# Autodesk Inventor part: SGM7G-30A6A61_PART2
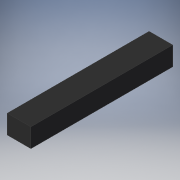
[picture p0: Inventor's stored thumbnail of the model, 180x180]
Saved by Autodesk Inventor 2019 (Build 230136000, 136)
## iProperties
Created: 2019-07
Part Number: SGM7G-30A6A61_PART2
Material: Generic
Catalog Web Link: www.cadenas.de
Description: -
Vendor: YASKAWAUSA
Document SubType Name: Modeling
Designer: psAdmin
Manufacturer: YASKAWAUSA
Mass: 4.8 g
Surface Area: 23.2 cm^2
Volume: 4.8 cm^3
Density: 1 g/cm^3
Appearance: PSOLRGB-175-175-175
Category: PARTsolutions
Company: YASKAWAUSA
Title: SGM7G-30A6A61_PART2
Author: Cadenas PARTsolutions
Sending System: PARTsolutions
PSOL_IDENT_0: {$CADENAS_DATA/23d-libs/yaskawa_usa/motion/sigma_7_servo_products/rotary_servo_motors/sgm7g.prj},198
PSOL_IDENT_1: {VTYP=3D},{NB=SGM7G-30A6A61_PART2},{LINA=SGM7G-30A6A61_PART2},{NN=SGM7G_PART2},{NOPRJ=TRUE},{DATE=2
PSOL_IDENT_2: 3.05.2022 13:08:23},{GEOMDATE=02.02.2021 08:21:09},{VERSION=},{LINEID=1400},{WBVAR=},{WBNUMERIC=}  {
PSOL_IDENT_3: NB=SGM7G-30A6A61_PART2},{LINA=SGM7G-30A6A61_PART2},{KT=DUMMY},{SHA256=Ki2iMjxjCAhV01RQo1wHrteAobWMX1
PSOL_IDENT_4: 4GeladcQJyvY8=},{INAME=00101__sgm7g_30a6a612estep},{PN=SGM7G-30A6A61},{DESC=S7 MTR 3.0KW 200V BAT-LE
PSOL_IDENT_5: SS ABS KW TP},{SERIES=7G},{RATO=3000},{SV=200},{SE=batteryless 24-bit absolute},{DR=A},{SHE=straight
PSOL_IDENT_6: with key and tap},{OPT=without options}
NB: SGM7G-30A6A61_PART2
NBSYN: $PN._PART2
LINA: SGM7G-30A6A61_PART2
CATALOG: Yaskawa
PN: SGM7G-30A6A61
DESC: S7 MTR 3.0KW 200V BAT-LESS ABS KW TP
SERIES: 7G
RATO: 3000
SV: 200
SE: batteryless 24-bit absolute
DR: A
SHE: straight with key and tap
OPT: without options
SUPPLIER: YASKAWAUSA
ARTICLENO: SGM7G-30A6A61_PART2
BOMINFO: SGM7G-30A6A61_PART2
CREATOR: CADENAS GmbH
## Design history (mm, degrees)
feature "NONE"
body "Solid1"
